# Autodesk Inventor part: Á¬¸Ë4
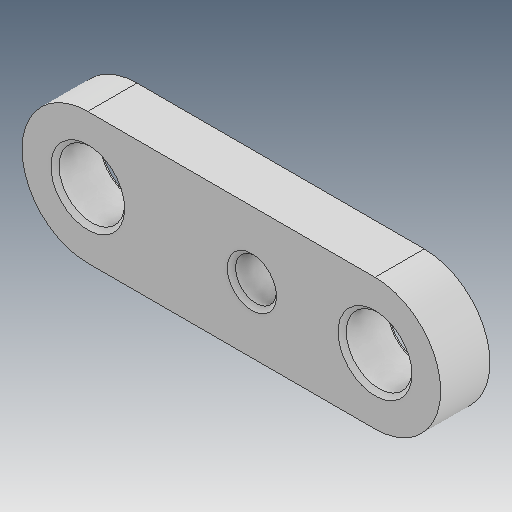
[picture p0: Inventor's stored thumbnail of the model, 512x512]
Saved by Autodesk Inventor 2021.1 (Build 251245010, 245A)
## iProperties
Created: 2013-04
Part Number: Á¬¸Ë4
Material: Ogólny
Document SubType Name: Modeling
Designer: user
Density: 1 g/cm^3
Appearance: Domyślna
Author: user
Revision Number: ÈÎºÎ
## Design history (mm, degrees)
feature "µ¹½Ç1"
node "Bryła1"
